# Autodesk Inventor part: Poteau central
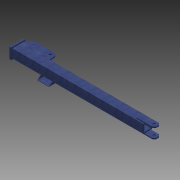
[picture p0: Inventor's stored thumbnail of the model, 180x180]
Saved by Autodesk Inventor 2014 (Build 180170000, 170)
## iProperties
Created: 2015-06
Part Number: Poteau central
Material: Générique
Document SubType Name: Modeling
Designer: OL
Density: 1 g/cm^3
Appearance: Par défaut
Author: OL
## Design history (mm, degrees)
sketch "Esquisse1"
  geometry: L1 (-40, 40)-(40, 40); L2 (40, 40)-(40, -40); L3 (40, -40)-(-40, -40); L4 (-40, -40)-(-40, 40); L5 (30, -30)-(-30, -30); L6 (-30, -30)-(-30, 30); L7 (-30, 30)-(30, 30); L8 (30, 30)-(30, -30); 1 further point
  constraints: 16 end point, 4 parallel, 2 horizontal, 2 perpendicular
  dimensions: "d0" = 40 distance from line of point (0, 0) L1; "d1" = 80 distance of L1.end L2.end; "d2" = 40 distance from line of L2 point (0, 0); "d3" = 80 distance of L1.start L1.end; "d4" = 10 distance between parallel lines of L1 L7; "d5" = 10 distance between parallel lines of L2 L8; "d6" = 10 distance between parallel lines of L3 L5; "d7" = 10 distance between parallel lines of L4 L6
extrude "Extrusion1" new body sketch "Esquisse1" distance "d8" = 1204; taper "d9" = 0 deg
sketch "Esquisse2"
  geometry: L1 (1204, 80)-(1204, 0) reference; L2 (0, 80)-(1204, 80) reference; L3 (1134, 70)-(1277, 70); L4 (1294, 53)-(1294, 27); L5 (1277, 10)-(1134, 10); L6 (1134, 10)-(1134, 70); L7 (1294, 53)-(1277, 70); L8 (1294, 27)-(1277, 10); C1 r 10 at (1264, 40); 1 further point
  constraints: 12 end point, 2 parallel, 1 centre point, 1 horizontal, 1 perpendicular
  dimensions: "d10" = 160 distance between parallel lines of L6 L4; "d12" = 60 distance between parallel lines of L3 L5; "d13" = 10 distance between parallel lines of L2 L3; "d14" = 17 horizontal distance of L4.start L3.end; "d15" = 17 horizontal distance of L4.start L3.end; "d16" = 17 horizontal distance of L4.end L5.start; "d17" = 17 horizontal distance of L4.end L5.start; "d18" = 70 distance between parallel lines of L1 L6; "d19" = 20 diameter of C1; "d20" = 30 distance from line of L4 C1.centre; "d21" = 30 distance from line of L5 C1.centre
extrude "Extrusion2" join sketch "Esquisse2" distance "d22" = 10; taper "d23" = 0 deg
mirror "Symétrie1"
sketch "Esquisse3"
  geometry: L1 (40, -40)-(40, 40) reference; L2 (-40, 40)-(-40, -40) reference; L3 (-40, -40)-(40, -40) reference; L4 (-50, -50)-(50, -50); L5 (50, -50)-(50, 70); L6 (30, 90)-(-30, 90); L7 (-50, 70)-(-50, -50); L8 (-50, 70)-(-30, 90); L9 (30, 90)-(50, 70); C1 r 7 at (0, 75); 1 further point
  constraints: 12 end point, 2 parallel, 1 centre point, 1 horizontal, 1 perpendicular
  dimensions: "d24" = 120 distance of L4.end L5.end; "d26" = 10 distance between parallel lines of L4 L3; "d27" = 10 distance between parallel lines of L5 L1; "d28" = 10 distance between parallel lines of L7 L2; "d29" = 20 horizontal distance of L6.start L5.end; "d30" = 20 horizontal distance of L6.start L5.end; "d31" = 20 horizontal distance of L7.start L6.end; "d32" = 20 horizontal distance of L7.start L6.end; "d33" = 75 distance of C1.centre point (0, 0); "d34" = 14 diameter of C1; "d35" = 50 distance from line of L5 C1.centre
extrude "Extrusion3" join sketch "Esquisse3" distance "d36" = 16; taper "d37" = 0 deg
sketch "Esquisse4"
  geometry: C1 r 27.5 at (0, 0); 1 further point
  constraints: 1 centre point, 1 coincident
  dimensions: "d38" = 55 diameter of C1
extrude "Extrusion4" cut sketch "Esquisse4" distance "d40" = 16; taper "d41" = 0 deg
sketch "Esquisse5"
  geometry: L1 (1204, 10)-(0, 10) reference; L2 (1204, 10)-(944, 10); L3 (944, 10)-(944, 50); L4 (984, 90)-(1154, 90); L5 (1204, 40)-(1204, 10); L6 (1154, 90)-(1204, 40); A1 r 40 centre (984, 50) between (984, 90) and (944, 50); 1 further point
  constraints: 10 end point, 3 point on circle, 2 parallel, 1 centre point, 1 horizontal, 1 perpendicular, 1 point on line, 1 tangent
  dimensions: "d45" = 50 horizontal distance of L4.end L5.start; "d46" = 50 horizontal distance of L4.end L5.start; "d47" = 40 distance from line of L2 A1.centre; "d48" = 40 radius of A1; "d49" = 260 distance between parallel lines of L5 L3; "d50" = 80 distance between parallel lines of L1 L4
extrude "Extrusion5" join sketch "Esquisse5" distance "d51" = 10; taper "d52" = 0 deg
mirror "Symétrie2"
sketch "Esquisse6"
  geometry: L1 (1154, 90)-(984, 90) reference; L2 (944, 50)-(944, 10) reference; C1 r 10 at (979, 55); 1 further point
  constraints: 1 centre point
  dimensions: "d53" = 20 diameter of C1; "d55" = 35 distance from line of L1 C1.centre; "d56" = 35 distance from line of L2 C1.centre
extrude "Extrusion6" cut sketch "Esquisse6" stored distance "d57" = 10; taper "d58" = 0 deg
sketch "Esquisse7"
  geometry: L1 (-1204, 0)-(0, 0) reference; L2 (-836, 0)-(-836, -27); L3 (-839, -30)-(-941, -30); L4 (-944, -27)-(-944, 0); L5 (-939, -26)-(-841, -26); L6 (-840, -25)-(-840, 0); L7 (-940, 0)-(-940, -25); L8 (-944, 0)-(-940, 0); L9 (-840, 0)-(-836, 0); A1 r 3 centre (-839, -27) between (-839, -30) and (-836, -27); A2 r 3 centre (-941, -27) between (-944, -27) and (-941, -30); A3 r 1 centre (-939, -25) between (-940, -25) and (-939, -26); A4 r 1 centre (-841, -25) between (-841, -26) and (-840, -25); 9 further points
  constraints: 16 end point, 11 point on line, 8 point on circle, 8 tangent, 4 centre point, 4 parallel, 2 horizontal, 2 perpendicular
  dimensions: "d59" = 0 distance from line of point (-944, 0) L4; "d60" = 108 distance of point (-944, -30) point (-836, -30); "d61" = 30 distance between parallel lines of L1 L3; "d63" = 4 distance between parallel lines of L3 L5; "d64" = 4 distance between parallel lines of L4 L7; "d65" = 4 distance between parallel lines of L2 L6; "d66" = 30 distance from line of L3 L6.end; "d85" = 3 radius of A2; "d86" = 1 radius of A3; "d87" = 3 radius of A1; "d89" = 1 radius of A4
extrude "Extrusion7" join sketch "Esquisse7" distance "d68" = 30; taper "d69" = 0 deg
sketch "Esquisse8"
  geometry: L1 (-944, 0)-(-944, 27) reference; L2 (-944, 0)-(-940, 0) reference; L3 (-940, 25)-(-940, 0) reference; L4 (-841, 26)-(-939, 26) reference; L5 (-840, 0)-(-840, 25) reference; L6 (-840, 0)-(-836, 0) reference; L7 (-836, 27)-(-836, 0) reference; L8 (-941, 30)-(-839, 30) reference; A1 r 3 centre (-839, 27) between (-836, 27) and (-839, 30) reference; A2 r 1 centre (-939, 25) between (-939, 26) and (-940, 25) reference; A3 r 1 centre (-841, 25) between (-840, 25) and (-841, 26) reference; A4 r 3 centre (-941, 27) between (-941, 30) and (-944, 27) reference; 1 further point
extrude "Extrusion10" join sketch "Esquisse8" distance "d91" = 180; taper "d92" = 0 deg
sketch "Esquisse12"
  geometry: L1 (0, 30)-(0, 0) reference; L2 (27, 0)-(0, 0) reference; L3 (0, 210)-(27, 210) reference; L4 (0, 110)-(0, 210) reference; L5 (30, 210)-(30, 0) reference; L6 (0, 210)-(30, 210); L7 (0, 210)-(0, 180); L8 (0, 30)-(0, 0); L9 (0, 0)-(30, 0); L10 (0, 30)-(26, 0); L11 (0, 180)-(26, 210); 1 further point
  constraints: 12 end point, 5 point on line, 3 collinear, 1 perpendicular
  dimensions: "d97" = 4 distance from line of L10.end L5; "d98" = 30 vertical distance of L8.start L10.end; "d99" = 4 distance from line of L5 L11.end; "d100" = 30 vertical distance of L11.start L11.end
extrude "Extrusion11" cut sketch "Esquisse12" distance "d95" = 110; taper "d96" = 0 deg
sketch "Esquisse13"
  geometry: L1 (0, 210)-(102, 210) reference; L2 (-3, 210)-(-3, 0) reference; C1 r 5.5 at (11, 190); C2 r 5.5 at (91, 190); C3 r 5.5 at (91, 20); C4 r 5.5 at (11, 20); 1 further point
  constraints: 4 centre point
  dimensions: "d101" = 11 diameter of C1; "d103" = 11 diameter of C2; "d104" = 11 diameter of C3; "d105" = 11 diameter of C4; "d106" = 170 distance of C3.centre C2.centre; "d107" = 80 distance of C2.centre C1.centre; "d108" = 80 distance of C4.centre C3.centre; "d109" = 170 distance of C1.centre C4.centre; "d110" = 170 vertical distance of C3.centre C1.centre; "d111" = 80 horizontal distance of C2.centre C4.centre; "d112" = 14 distance from line of L2 C1.centre; "d113" = 20 distance from line of L1 C1.centre
extrude "Extrusion12" cut sketch "Esquisse13" distance "d114" = 5; taper "d115" = 0 deg
node "Solide1"
